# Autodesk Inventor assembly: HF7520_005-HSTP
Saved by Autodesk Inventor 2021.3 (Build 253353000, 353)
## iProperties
Created: 2022-06
Part Number: HF7520_005-HSTP
Document SubType Name: Assembly
Designer: Administrator
Title: HF7520_005-HSTP
Author: Administrator
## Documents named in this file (2)
- c:\worker\convert-fusion-r03\tmp\job-1\203\output\files\98ba3c1f-9f0e-47fe-8659-38db50984f0d\HF7520_005-HSTP.iam
- c:\worker\convert-fusion-r03\tmp\job-1\203\output\files\98ba3c1f-9f0e-47fe-8659-38db50984f0d\COMPOUND.ipt
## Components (1 placed, 1 different names)
1. COMPOUND:1
